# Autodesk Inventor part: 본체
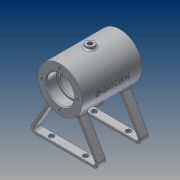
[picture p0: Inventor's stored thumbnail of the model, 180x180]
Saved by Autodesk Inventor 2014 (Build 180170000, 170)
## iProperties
Created: 2016-03
Part Number: 본체
Material: 알루미늄 6061
Document SubType Name: Modeling
Designer: 703-15
Density: 2.71 g/cm^3
Appearance: 알루미늄 - 평지
Mass: 211.809 g
Surface Area: 337.429 cm^2
Volume: 78.1583 cm^3
Author: 703-15
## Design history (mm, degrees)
sketch "스케치1"
  geometry: C1 r 26 at (0, 0); C2 r 16 at (0, 0); 1 further point
  constraints: 2 centre point, 2 coincident
  dimensions: "d0" = 52 diameter of C1; "d1" = 32 diameter of C2
extrude "돌출1" new body sketch "스케치1" stored distance "d2" = 70; taper "d3" = 0 deg
sketch "스케치2"
  geometry: 2 further points
  constraints: 1 vertical alignment
  dimensions: "d4" = 21 distance of point (0, 0) point (0, 21)
hole "구멍1" sketch "스케치2" at (0, 21) diameter "d5" = 3.242; stored, may be unused: countersink angle "d9" = 90 deg, drill point angle "d11" = 118 deg; dims "d6" = 8, "d7" = 4, "d8" = 2, "d10" = 10
node "작업 평면1"
sketch "스케치3"
  geometry: L1 (-16.613, -20)-(-38.264, -57.5); L2 (-33.934, -65)-(33.934, -65); L3 (38.264, -57.5)-(16.613, -20); L4 (0, 26)-(0, -65); L5 (14.183, -21.791)-(35.666, -59); L6 (33.934, -62)-(-33.934, -62); L7 (-35.666, -59)-(-14.183, -21.791); A1 r 26 centre (0, 0) between (-16.613, -20) and (16.613, -20) reference; A2 r 5 centre (-33.934, -60) between (-38.264, -57.5) and (-33.934, -65); A3 r 5 centre (33.934, -60) between (33.934, -65) and (38.264, -57.5); A4 r 2 centre (33.934, -60) between (33.934, -62) and (35.666, -59); A5 r 2 centre (-33.934, -60) between (-35.666, -59) and (-33.934, -62); 3 further points
  constraints: 14 end point, 13 point on circle, 4 centre point, 4 point on line, 4 tangent, 1 equal radius, 1 horizontal, 1 midpoint, 1 perpendicular, 2 other
  dimensions: "d16" = 65 vertical distance of point (42.594, -65) point (0, 0); "d17" = 30 deg angle of L3 L4; "d18" = 30 deg angle of L4 L1; "d19" = 45 vertical distance of L3.end point (42.594, -65); "d20" = 45 vertical distance of point (-42.594, -65) L1.start (= d19); "d21" = 5 radius of A2; "d22" = 3 distance between parallel lines of L3 L5; "d23" = 3 distance between parallel lines of L1 L7; "d24" = 3 distance between parallel lines of L6 L2
extrude "돌출2" join sketch "스케치3" distance "d25" = 10; taper "d26" = 0 deg
sketch "스케치4"
  geometry: C1 r 21 at (0, 0); 1 further point
  constraints: 1 centre point, 1 coincident
  dimensions: "d27" = 42 diameter of C1
extrude "돌출3" cut sketch "스케치4" stored distance "d28" = 42; taper "d29" = 0 deg
node "작업 평면2"
sketch "스케치5"
  geometry: C1 r 14 at (0, 0); C2 r 16 at (0, 0); 1 further point
  constraints: 2 centre point, 2 coincident
  dimensions: "d31" = 28 diameter of C1; "d32" = 32 diameter of C2
extrude "돌출4" join sketch "스케치5" distance "d33" = 2; taper "d34" = 0 deg
fillet "모깎기1" dims "d35" = 0.3, "d46" = 0.5
sketch "스케치6"
  geometry: L1 (0, 10)-(67.868, 10) reference; 3 further points
  constraints: 1 horizontal alignment
  dimensions: "d36" = 20 horizontal distance of point (33.934, -20) point (13.934, 5); "d37" = 20 horizontal distance of point (33.934, -20) point (53.934, 5) (= d36); "d38" = 5 distance from line of L1 point (53.934, 5)
hole "구멍2" sketch "스케치6" at (13.934, 5), (53.934, 5) diameter "d39" = 6; stored, may be unused: countersink angle "d43" = 90 deg, drill point angle "d45" = 118 deg; dims "d40" = 8, "d41" = 4, "d42" = 2, "d44" = 10
node "작업 평면3"
sketch "스케치7"
  geometry: C1 r 5 at (0, 0); 1 further point
  constraints: 1 centre point, 1 coincident
  dimensions: "d48" = 10 diameter of C1
extrude "돌출5" join sketch "스케치7" stored distance "d49" = 2; taper "d50" = 0 deg
hole "구멍3" diameter "d53" = 5.188; stored, may be unused: countersink angle "d57" = 90 deg, drill point angle "d59" = 0 deg; dims "d54" = 6, "d55" = 4, "d56" = 2, "d58" = 10, "d76" = 10, "d77" = 10
sketch "스케치8"
  geometry: C1 r 6 at (0, 0); C2 r 5 at (0, 0) reference; 1 further point
  constraints: 1 centre point, 1 coincident
  dimensions: "d63" = 12 diameter of C1
extrude "돌출6" join sketch "스케치8" stored distance "d64" = 2; taper "d65" = 0 deg
fillet "모깎기2" dims "d66" = 2, "d67" = 3
node "작업 평면4"
sketch "스케치9"
  geometry: L1 (26, -35)-(26, 35) reference; L2 (26, 35)-(-26, 35) reference; 2 further points
  constraints: 1 other
  dimensions: "d69" = 26 distance from line of L1 point (0, 0); "d70" = 35 distance from line of point (0, 0) L2
feature "엠보싱1" sketch "스케치9" dims "d16" = 65, "d17" = 30 deg, "d18" = 30 deg, "d19" = 45, "d20" = 45 (= d19), "d21" = 5, "d22" = 3, "d23" = 3, "d24" = 3, "d71" = 0.5, "d72" = 0
chamfer "모따기1" distance "d73" = 1; stored, may be unused: second distance "d74" = 2, angle "d75" = 45 deg
node "솔리드1"
pattern_circular "원형 패턴1" dims angle "d13" = 360 deg
mirror "대칭1"
mirror "대칭2"
mirror "대칭3"
mirror "대칭4"
pattern_circular "원형 패턴2" dims angle "d61" = -165 deg
other parameters: "d30" = 21, "d47" = 29, "d68" = 26
